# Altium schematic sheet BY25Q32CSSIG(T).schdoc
size 127 x 101 mm
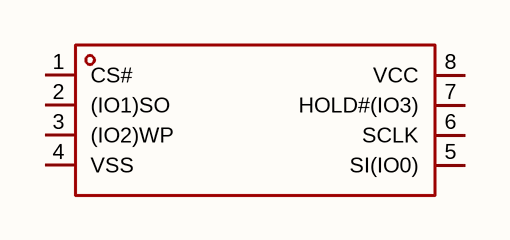
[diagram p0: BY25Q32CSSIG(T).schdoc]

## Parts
U?  by25q32cssig(t)  [SOIC-8_L5.3-W5.3-P1.27-LS7.9-BL]  (value not drawn)

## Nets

Not connected (* = marked no-connect by the designer): U? 1(CS#) 2((IO1)SO) 3((IO2)WP) 4(VSS) 5(SI(IO0)) 6(SCLK) 7(HOLD#(IO3)) 8(VCC)

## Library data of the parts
U? = by25q32cssig(t): 接口类型:SPI;存储容量:32Mbit;时钟频率(fc):108MHz;; Manufacturer: BOYAMICRO(博雅); AddInBom: yes; ModelId: 78e311bc6cdb4f2a8ea91f8efea56c7d; ModelTransform: 311.023,207.8736,0,90,0,0,0,0,0; Interface: SPI; Memory Size: 32Mbit; Clock Frequency: 108MHz; Voltage - Supply: 2.7V~3.6V; Standby Supply Current: 5uA; Program / Erase Cycles: 100000次; Page Programming Time (Tpp): 600us; Block Erase Time(tBE): 150ms; Data Retention - TDR (Year): 20年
